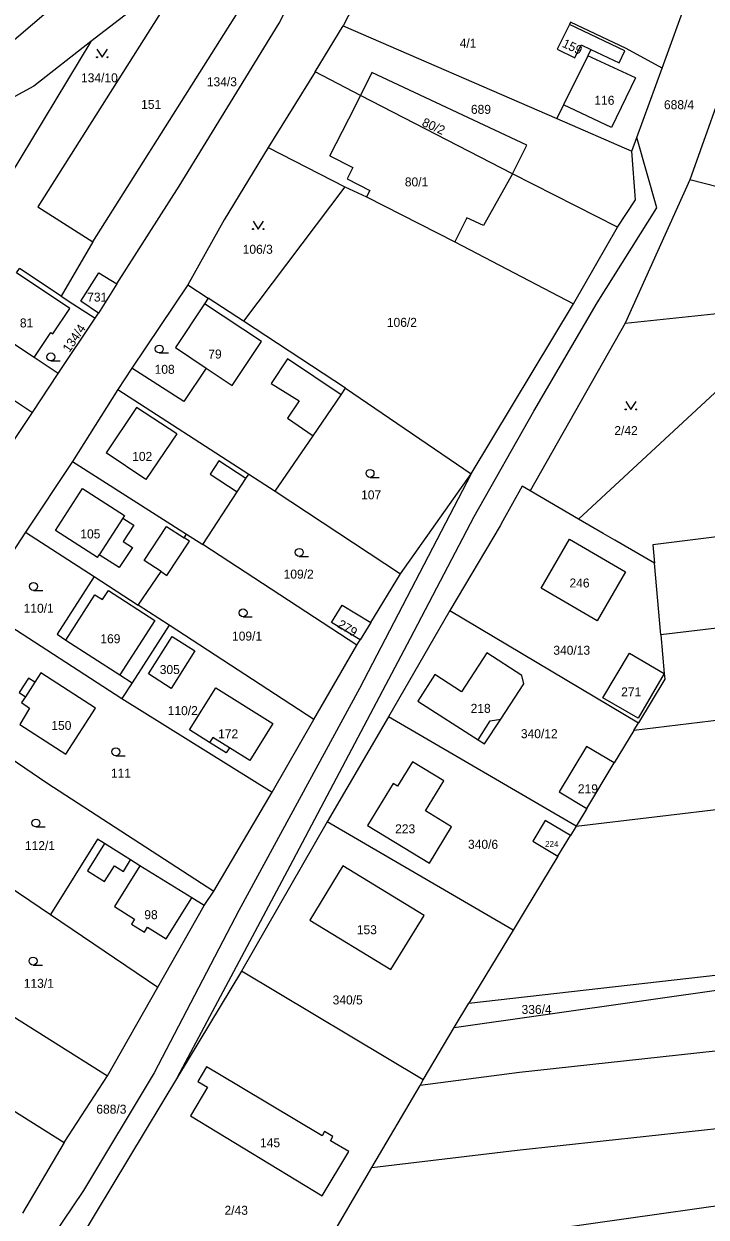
# Model space of a CAD drawing. Extents: x -7483133 to -743907, y -11317770 to -1129777.
# Drawn here: x -746238.8 to -746109.8, y -1131825.9 to -1131600.2 of the extents above; entities that cross this region are included whole.
import ezdxf

# ---------------------------------------------------------------- set-up
doc = ezdxf.new("R2010")
doc.units = 0
for name, color, linetype in [('Hranice parcel', 7, 'Continuous'), ('Parcelní čísla', 7, 'Continuous'), ('Vnitřní kresba', 7, 'Continuous'), ('Značky kultur', 7, 'Continuous')]:
    doc.layers.add(name, color=color, linetype=linetype)

msp = doc.modelspace()

# ---------------------------------------------------------------- linework, layer by layer
at = {"layer": 'Hranice parcel'}
for p, q in [((-746169.3, -1131582.67), (-746178.46, -1131600.58)), ((-746209.75, -1131590.87), (-746226.17, -1131603.55)), ((-746118.15, -1131608.57), (-746111.97, -1131591.58)), ((-746183.74, -1131609.25), (-746178.46, -1131600.58)), ((-746178.46, -1131600.58), (-746138.05, -1131618.07)), ((-746135.43, -1131599.84), (-746135.65, -1131600.29)), ((-746226.17, -1131603.55), (-746248.59, -1131640.59)), ((-746104.52, -1131606.12), (-746112.88, -1131629.7)), ((-746183.74, -1131609.25), (-746192.62, -1131623.6)), ((-746175.19, -1131613.74), (-746183.74, -1131609.25)), ((-746122.9, -1131621.67), (-746118.15, -1131608.57)), ((-746146.41, -1131628.53), (-746175.19, -1131613.74)), ((-746138.05, -1131618.07), (-746123.85, -1131624.29)), ((-746123.85, -1131624.29), (-746122.9, -1131621.67)), ((-746192.62, -1131623.6), (-746178.11, -1131631.02)), ((-746126.56, -1131638.66), (-746146.41, -1131628.53)), ((-746112.88, -1131629.7), (-746125.11, -1131656.77)), ((-746096.04, -1131633.97), (-746112.88, -1131629.7)), ((-746178.11, -1131631.02), (-746197.29, -1131656.44)), ((-746134.91, -1131653.16), (-746126.56, -1131638.66)), ((-746225.82, -1131641.41), (-746231.78, -1131651.66)), ((-746231.78, -1131651.66), (-746239.66, -1131646.47)), ((-746221.25, -1131649.38), (-746224.73, -1131654.87)), ((-746207.82, -1131649.53), (-746218.4, -1131665.32)), ((-746207.82, -1131649.53), (-746203.97, -1131652.06)), ((-746203.97, -1131652.06), (-746204.68, -1131653.13)), ((-746197.29, -1131656.44), (-746203.97, -1131652.06)), ((-746154.22, -1131685.29), (-746134.91, -1131653.16)), ((-746125.11, -1131656.77), (-746090.01, -1131653.11)), ((-746225.37, -1131655.87), (-746224.73, -1131654.87)), ((-746232.33, -1131666.33), (-746225.37, -1131655.87)), ((-746178.01, -1131669.1), (-746197.29, -1131656.44)), ((-746125.11, -1131656.77), (-746143.09, -1131688.51)), ((-746254.86, -1131661.98), (-746237.23, -1131673.69)), ((-746237.23, -1131673.69), (-746232.33, -1131666.33)), ((-746218.4, -1131665.32), (-746221.07, -1131669.31)), ((-746208.6, -1131671.63), (-746218.4, -1131665.32)), ((-746133.92, -1131693.84), (-746104.37, -1131666.43)), ((-746221.07, -1131669.31), (-746229.64, -1131682.94)), ((-746221.07, -1131669.31), (-746196.29, -1131685.32)), ((-746178.84, -1131670.33), (-746178.01, -1131669.1)), ((-746178.01, -1131669.1), (-746154.22, -1131685.29)), ((-746184.1, -1131678.09), (-746178.84, -1131670.33)), ((-746248.85, -1131691.18), (-746237.23, -1131673.69)), ((-746191.3, -1131688.55), (-746184.1, -1131678.09)), ((-746229.64, -1131682.94), (-746238.54, -1131696.32)), ((-746229.64, -1131682.94), (-746208.05, -1131696.69)), ((-746198.48, -1131688.67), (-746196.84, -1131686.16)), ((-746196.84, -1131686.16), (-746196.29, -1131685.32)), ((-746196.29, -1131685.32), (-746191.3, -1131688.55)), ((-746167.6, -1131704.18), (-746154.22, -1131685.29)), ((-746012.9, -1131685.16), (-746119.9, -1131698.71)), ((-746205.01, -1131698.62), (-746198.48, -1131688.67)), ((-746191.3, -1131688.55), (-746167.6, -1131704.18)), ((-746133.92, -1131693.84), (-746143.09, -1131688.51)), ((-746238.54, -1131696.32), (-746247.57, -1131710.13)), ((-746238.54, -1131696.32), (-746225.54, -1131704.73)), ((-746211.79, -1131704.5), (-746207.53, -1131698.01)), ((-746208.05, -1131696.69), (-746205.01, -1131698.62)), ((-746175.84, -1131717.7), (-746205.01, -1131698.62)), ((-746119.9, -1131698.71), (-746119.59, -1131702.16)), ((-746118.38, -1131715.73), (-746119.59, -1131702.16)), ((-746225.54, -1131704.73), (-746232.57, -1131715.63)), ((-746225.54, -1131704.73), (-746217.23, -1131710.1)), ((-746173.21, -1131713.39), (-746167.6, -1131704.18)), ((-746247.57, -1131710.13), (-746220.28, -1131727.78)), ((-746211.35, -1131713.91), (-746217.23, -1131710.1)), ((-746180.67, -1131713.43), (-746178.65, -1131710.15)), ((-746178.65, -1131710.15), (-746173.21, -1131713.39)), ((-746158.27, -1131711.14), (-746169.89, -1131731.23)), ((-746158.27, -1131711.14), (-746122.58, -1131732.37)), ((-746211.35, -1131713.91), (-746218.35, -1131724.78)), ((-746183.97, -1131731.72), (-746211.35, -1131713.91)), ((-746175.23, -1131716.7), (-746180.67, -1131713.43)), ((-746173.21, -1131713.39), (-746175.23, -1131716.7)), ((-746175.84, -1131717.7), (-746175.23, -1131716.7)), ((-746118.38, -1131715.73), (-746117.73, -1131723.06)), ((-746183.97, -1131731.72), (-746175.84, -1131717.7)), ((-746009.74, -1131720.07), (-746123.47, -1131733.84)), ((-746220.68, -1131723.28), (-746218.35, -1131724.78)), ((-746218.35, -1131724.78), (-746220.28, -1131727.78)), ((-746220.28, -1131727.78), (-746191.89, -1131745.5)), ((-746191.89, -1131745.5), (-746183.97, -1131731.72)), ((-746169.89, -1131731.23), (-746181.5, -1131751.09)), ((-746134.41, -1131751.93), (-746169.89, -1131731.23)), ((-746123.47, -1131733.84), (-746122.58, -1131732.37)), ((-746123.47, -1131733.84), (-746127.17, -1131739.96)), ((-746132.45, -1131736.84), (-746137.57, -1131745.44)), ((-746134.41, -1131751.93), (-746008.22, -1131736.82)), ((-746127.17, -1131739.96), (-746132.45, -1131736.84)), ((-746132.37, -1131748.55), (-746127.17, -1131739.96)), ((-746202.88, -1131764.19), (-746191.89, -1131745.5)), ((-746137.57, -1131745.44), (-746132.37, -1131748.55)), ((-746132.37, -1131748.55), (-746134.41, -1131751.93)), ((-746181.5, -1131751.09), (-746197.7, -1131779.34)), ((-746146.31, -1131771.57), (-746181.5, -1131751.09)), ((-746140.23, -1131750.83), (-746142.61, -1131754.73)), ((-746135.47, -1131753.68), (-746140.23, -1131750.83)), ((-746134.41, -1131751.93), (-746135.47, -1131753.68)), ((-746142.61, -1131754.73), (-746137.83, -1131757.57)), ((-746137.83, -1131757.57), (-746135.47, -1131753.68)), ((-746247.71, -1131759.28), (-746233.81, -1131768.65)), ((-746178.52, -1131759.43), (-746184.77, -1131769.7)), ((-746204.77, -1131766.94), (-746207.1, -1131765.49)), ((-746204.77, -1131766.94), (-746202.88, -1131764.19)), ((-746213.53, -1131782.34), (-746204.77, -1131766.94)), ((-746157.45, -1131789.98), (-746005.35, -1131768.4)), ((-746154.67, -1131785.39), (-746005.35, -1131768.4)), ((-746233.81, -1131768.65), (-746213.53, -1131782.34)), ((-746146.31, -1131771.57), (-746154.67, -1131785.39)), ((-746256.85, -1131777.8), (-746223.05, -1131799.15)), ((-746197.7, -1131779.34), (-746209.77, -1131799.39)), ((-746163.29, -1131799.92), (-746197.7, -1131779.34)), ((-746223.05, -1131799.15), (-746213.53, -1131782.34)), ((-746157.45, -1131789.98), (-746154.67, -1131785.39)), ((-746264.99, -1131790.48), (-746231.2, -1131811.77)), ((-746163.29, -1131799.92), (-746157.45, -1131789.98)), ((-746231.2, -1131811.77), (-746223.05, -1131799.15)), ((-746209.77, -1131799.39), (-746228.3, -1131830.15)), ((-746163.91, -1131800.98), (-746163.29, -1131799.92)), ((-746173.02, -1131816.46), (-746163.91, -1131800.98)), ((-746231.2, -1131811.77), (-746239.12, -1131825.11)), ((-746182.24, -1131832.12), (-746173.02, -1131816.46))]:
    msp.add_line(p, q, dxfattribs=at)
for points in [[(-746221.25, -1131649.38), (-746209.49, -1131630.87), (-746190.58, -1131600.07), (-746179.04, -1131577.6), (-746173.33, -1131568.01)], [(-746196.48, -1131579.32), (-746203.74, -1131591.04), (-746207.17, -1131588.88), (-746236.19, -1131634.81), (-746225.82, -1131641.41)], [(-746225.82, -1131641.41), (-746196.77, -1131595.45), (-746188.95, -1131583.07)], [(-746220.35, -1131585.87), (-746245.48, -1131607.32), (-746260.07, -1131614.14)], [(-746135.65, -1131600.29), (-746137.95, -1131605), (-746134.65, -1131606.61), (-746133.46, -1131604.17), (-746131.63, -1131605.04)], [(-746131.63, -1131605.04), (-746126.28, -1131607.58), (-746125.18, -1131605.31), (-746135.65, -1131600.29)], [(-746118.15, -1131608.57), (-746124.96, -1131604.86), (-746135.43, -1131599.84)], [(-746226.17, -1131603.55), (-746236.96, -1131611.95), (-746251.98, -1131620.08)], [(-746131.63, -1131605.04), (-746132.2, -1131606.23), (-746136.79, -1131615.51), (-746138.05, -1131618.07)], [(-746146.41, -1131628.53), (-746143.73, -1131623.16), (-746173.04, -1131609.37), (-746175.19, -1131613.74)], [(-746209.77, -1131799.39), (-746188.47, -1131759.43), (-746165.71, -1131716.39), (-746153.65, -1131693.34), (-746142.41, -1131673.43), (-746130.42, -1131652.96), (-746119.1, -1131634.98), (-746122.9, -1131621.67)], [(-746192.62, -1131623.6), (-746200.96, -1131637.27), (-746207.82, -1131649.53)], [(-746126.56, -1131638.66), (-746123.16, -1131633.44), (-746123.85, -1131624.29)], [(-746178.11, -1131631.02), (-746174.04, -1131632.93), (-746157.34, -1131641.42), (-746134.91, -1131653.16)], [(-746232.33, -1131666.33), (-746236.91, -1131663.29), (-746233.75, -1131658.54), (-746233.36, -1131658.8), (-746230.15, -1131654.01), (-746240.2, -1131647.27), (-746239.66, -1131646.47)], [(-746224.73, -1131654.87), (-746228.08, -1131652.63), (-746224.65, -1131647.29), (-746221.25, -1131649.38)], [(-746231.78, -1131651.66), (-746229.55, -1131653.12), (-746225.37, -1131655.87)], [(-746204.68, -1131653.13), (-746210.15, -1131661.38), (-746204.34, -1131665.28), (-746208.6, -1131671.63)], [(-746154.22, -1131685.29), (-746175.35, -1131725.88), (-746198.19, -1131767.85), (-746214.17, -1131798.54), (-746227.58, -1131820.8), (-746249.27, -1131852.92), (-746268.11, -1131879.9), (-746296.61, -1131921.49), (-746301.25, -1131926.61)], [(-746143.09, -1131688.51), (-746144.59, -1131687.64), (-746148.26, -1131694.19), (-746148.79, -1131695.13), (-746158.27, -1131711.14)], [(-746119.59, -1131702.16), (-746127.06, -1131697.82), (-746129.27, -1131696.54), (-746133.92, -1131693.84)], [(-746207.53, -1131698.01), (-746208.52, -1131697.37), (-746208.05, -1131696.69)], [(-746125.05, -1131703.81), (-746130.42, -1131713.06), (-746140.98, -1131706.93), (-746135.62, -1131697.67), (-746125.05, -1131703.81)], [(-746011.28, -1131703.02), (-746082.88, -1131711.52), (-746090.83, -1131712.46), (-746118.38, -1131715.73)], [(-746217.23, -1131710.1), (-746212.9, -1131703.77), (-746211.79, -1131704.5)], [(-746232.57, -1131715.63), (-746230.88, -1131716.72), (-746220.68, -1131723.28)], [(-746206.49, -1131718.76), (-746210.97, -1131725.86), (-746215.29, -1131723.08), (-746210.77, -1131716.05), (-746206.49, -1131718.76)], [(-746161.12, -1131723.26), (-746164.36, -1131728.28), (-746152.94, -1131735.58), (-746151.74, -1131736.35), (-746148.66, -1131731.66), (-746144.31, -1131725.02), (-746144.66, -1131723.4), (-746151.26, -1131719.11), (-746156.08, -1131726.53), (-746161.12, -1131723.26)], [(-746117.73, -1131723.06), (-746122.65, -1131731.51), (-746129.35, -1131727.65), (-746124.3, -1131719.23), (-746117.73, -1131723.06)], [(-746230.93, -1131738.3), (-746225.29, -1131729.6), (-746235.61, -1131722.9), (-746236.77, -1131724.69), (-746237.95, -1131723.93), (-746239.73, -1131726.67), (-746238.56, -1131727.43), (-746239.28, -1131728.55), (-746237.75, -1131729.59), (-746239.58, -1131732.69), (-746230.93, -1131738.3)], [(-746117.73, -1131723.06), (-746117.64, -1131724.09), (-746122.58, -1131732.37)], [(-746199.96, -1131737.11), (-746200.56, -1131738.06), (-746203.72, -1131736.08), (-746207.52, -1131733.7), (-746202.54, -1131725.73), (-746191.73, -1131732.48), (-746196.12, -1131739.51), (-746199.96, -1131737.11)], [(-746241.4, -1131739.01), (-746234.47, -1131743.75), (-746202.88, -1131764.19)], [(-746162.14, -1131758.91), (-746157.95, -1131752.03), (-746162.91, -1131749), (-746159.44, -1131743.32), (-746165.34, -1131739.72), (-746168.15, -1131744.36), (-746169.01, -1131743.85), (-746173.86, -1131751.77), (-746162.14, -1131758.91)], [(-746223.6, -1131755.22), (-746224.93, -1131754.39), (-746233.81, -1131768.65)], [(-746207.1, -1131765.49), (-746216.88, -1131759.41), (-746218.64, -1131758.31), (-746223.6, -1131755.22)], [(-746184.77, -1131769.7), (-746169.46, -1131779.05), (-746163.11, -1131768.8), (-746178.52, -1131759.43)], [(-746137.83, -1131757.57), (-746144.01, -1131767.78), (-746146.31, -1131771.57)], [(-745872.82, -1131767.1), (-745913.22, -1131772.23), (-746038.67, -1131786.65), (-746091.32, -1131792.64), (-746145.12, -1131798.49), (-746163.91, -1131800.98)], [(-746173.02, -1131816.46), (-746145.54, -1131813.2), (-746104.87, -1131808.78), (-746061.62, -1131803.78), (-746009.82, -1131797.07), (-745872.32, -1131782.29)], [(-746180.84, -1131811.4), (-746180.38, -1131810.62), (-746181.95, -1131809.69), (-746182.41, -1131810.46), (-746202.46, -1131798.53), (-746204.31, -1131797.43), (-746205.95, -1131800.2), (-746204.11, -1131801.3), (-746207.33, -1131806.71)], [(-746182.24, -1131832.12), (-746144.56, -1131828.9), (-746105.32, -1131823.34), (-745952.05, -1131805.35), (-745871.83, -1131797.13)], [(-746207.33, -1131806.71), (-746182.44, -1131821.82), (-746177.39, -1131813.45), (-746180.84, -1131811.4)]]:
    msp.add_lwpolyline(points, dxfattribs=at)
at = {"layer": 'Vnitřní kresba'}
for p, q in [((-746123.14, -1131610.41), (-746132.2, -1131606.23)), ((-746123.14, -1131610.41), (-746127.73, -1131619.82)), ((-746176.18, -1131615.83), (-746175.19, -1131613.74)), ((-746180.96, -1131625.14), (-746176.18, -1131615.83)), ((-746127.73, -1131619.82), (-746136.79, -1131615.51)), ((-746180.96, -1131625.14), (-746176.62, -1131627.37)), ((-746176.62, -1131627.37), (-746177.72, -1131629.52)), ((-746146.41, -1131628.53), (-746151.91, -1131638.33)), ((-746177.72, -1131629.52), (-746173.42, -1131631.72)), ((-746173.42, -1131631.72), (-746174.04, -1131632.93)), ((-746155.06, -1131636.85), (-746157.34, -1131641.42)), ((-746151.91, -1131638.33), (-746155.06, -1131636.85)), ((-746193.87, -1131660.27), (-746204.68, -1131653.13)), ((-746236.91, -1131663.29), (-746244.15, -1131658.48)), ((-746199.42, -1131668.58), (-746193.87, -1131660.27)), ((-746188.96, -1131663.55), (-746192.08, -1131668.2)), ((-746178.84, -1131670.33), (-746188.96, -1131663.55)), ((-746204.34, -1131665.28), (-746199.42, -1131668.58)), ((-746192.08, -1131668.2), (-746186.79, -1131671.5)), ((-746186.79, -1131671.5), (-746189, -1131674.77)), ((-746217.55, -1131672.77), (-746223.27, -1131681.3)), ((-746209.89, -1131677.72), (-746217.55, -1131672.77)), ((-746189, -1131674.77), (-746184.1, -1131678.09)), ((-746209.89, -1131677.72), (-746215.75, -1131686.34)), ((-746215.75, -1131686.34), (-746223.27, -1131681.3)), ((-746201.94, -1131682.81), (-746203.59, -1131685.32)), ((-746196.84, -1131686.16), (-746201.94, -1131682.81)), ((-746203.59, -1131685.32), (-746198.48, -1131688.67)), ((-746232.86, -1131696.03), (-746227.77, -1131688.09)), ((-746227.77, -1131688.09), (-746219.83, -1131693.18)), ((-746220.13, -1131693.65), (-746224.59, -1131700.61)), ((-746219.83, -1131693.18), (-746220.13, -1131693.65)), ((-746220.13, -1131693.65), (-746218.05, -1131694.98)), ((-746224.92, -1131701.12), (-746232.86, -1131696.03)), ((-746218.05, -1131694.98), (-746220.04, -1131698.08)), ((-746216.08, -1131701.68), (-746211.84, -1131695.22)), ((-746211.84, -1131695.22), (-746208.52, -1131697.37)), ((-746220.04, -1131698.08), (-746218.3, -1131699.2)), ((-746224.92, -1131701.12), (-746224.59, -1131700.61)), ((-746220.81, -1131703.03), (-746224.59, -1131700.61)), ((-746218.3, -1131699.2), (-746220.81, -1131703.03)), ((-746212.9, -1131703.77), (-746216.08, -1131701.68)), ((-746223.99, -1131709.08), (-746222.85, -1131707.37)), ((-746222.85, -1131707.37), (-746214.04, -1131713.03)), ((-746230.88, -1131716.72), (-746225.39, -1131708.18)), ((-746225.39, -1131708.18), (-746223.99, -1131709.08)), ((-746214.04, -1131713.03), (-746220.68, -1131723.28)), ((-746236.77, -1131724.69), (-746238.56, -1131727.43)), ((-746152.94, -1131735.58), (-746150.67, -1131732.02)), ((-746150.67, -1131732.02), (-746148.66, -1131731.66)), ((-746203.13, -1131735.12), (-746203.72, -1131736.08)), ((-746199.96, -1131737.11), (-746203.13, -1131735.12)), ((-746223.6, -1131755.22), (-746226.83, -1131760.34)), ((-746223.56, -1131762.38), (-746221.68, -1131759.43)), ((-746216.88, -1131759.41), (-746221.71, -1131767.14)), ((-746221.68, -1131759.43), (-746219.99, -1131760.48)), ((-746219.99, -1131760.48), (-746218.64, -1131758.31)), ((-746226.83, -1131760.34), (-746223.56, -1131762.38)), ((-746211.93, -1131773.21), (-746207.1, -1131765.49)), ((-746221.71, -1131767.14), (-746217.93, -1131769.49)), ((-746217.93, -1131769.49), (-746218.51, -1131770.42)), ((-746218.51, -1131770.42), (-746216.05, -1131771.94)), ((-746216.05, -1131771.94), (-746215.47, -1131771.01)), ((-746215.47, -1131771.01), (-746211.93, -1131773.21))]:
    msp.add_line(p, q, dxfattribs=at)
at = {"layer": 'Značky kultur'}
for p, q in [((-746213.23, -1131662.43), (-746211.48, -1131662.43)), ((-746233.74, -1131663.93), (-746231.99, -1131663.93)), ((-746173.37, -1131685.96), (-746171.62, -1131685.96)), ((-746186.75, -1131700.89), (-746185, -1131700.89)), ((-746237.02, -1131707.33), (-746235.27, -1131707.33)), ((-746197.38, -1131712.32), (-746195.63, -1131712.32)), ((-746221.44, -1131738.59), (-746219.69, -1131738.59)), ((-746236.55, -1131752.07), (-746234.8, -1131752.07)), ((-746237.09, -1131778.18), (-746235.34, -1131778.18))]:
    msp.add_line(p, q, dxfattribs=at)
for points in [[(-746225.01, -1131605), (-746224.01, -1131606.5), (-746223.01, -1131605)], [(-746195.5, -1131637.5), (-746194.5, -1131639), (-746193.5, -1131637.5)], [(-746125.02, -1131671.61), (-746124.02, -1131673.11), (-746123.02, -1131671.61)]]:
    msp.add_lwpolyline(points, dxfattribs=at)
for centre, radius in [((-746225.01, -1131606.5), 0.1), ((-746223.01, -1131606.5), 0.1), ((-746195.5, -1131639), 0.1), ((-746193.5, -1131639), 0.1), ((-746233.74, -1131663.18), 0.75), ((-746213.23, -1131661.68), 0.75), ((-746125.02, -1131673.11), 0.1), ((-746123.02, -1131673.11), 0.1), ((-746173.37, -1131685.21), 0.75), ((-746186.75, -1131700.14), 0.75), ((-746237.02, -1131706.58), 0.75), ((-746197.38, -1131711.57), 0.75), ((-746221.44, -1131737.84), 0.75), ((-746236.55, -1131751.32), 0.75), ((-746237.09, -1131777.43), 0.75)]:
    msp.add_circle(centre, radius, dxfattribs=at)

# ---------------------------------------------------------------- texts
at = {"layer": 'Parcelní čísla'}
for s, height, p in [('4/1', 1.7, (-746156.41, -1131604.7)), ('134/10', 1.7, (-746228.03, -1131611.24)), ('134/3', 1.7, (-746204.23, -1131611.99)), ('151', 1.7, (-746216.66, -1131616.27)), ('116', 1.7, (-746130.94, -1131615.49)), ('688/4', 1.7, (-746117.78, -1131616.33)), ('689', 1.7, (-746154.29, -1131617.21)), ('80/1', 1.7, (-746166.79, -1131630.93)), ('106/3', 1.7, (-746197.45, -1131643.67)), ('731', 1.7, (-746226.86, -1131652.71)), ('106/2', 1.7, (-746170.19, -1131657.49)), ('81', 1.7, (-746239.59, -1131657.6)), ('79', 1.7, (-746203.96, -1131663.48)), ('108', 1.7, (-746214.11, -1131666.37)), ('2/42', 1.7, (-746127.17, -1131677.96)), ('102', 1.7, (-746218.35, -1131682.84)), ('107', 1.7, (-746175.06, -1131690.11)), ('105', 1.7, (-746228.16, -1131697.5)), ('109/2', 1.7, (-746189.71, -1131705.1)), ('246', 1.7, (-746135.65, -1131706.78)), ('110/1', 1.7, (-746238.88, -1131711.56)), ('169', 1.7, (-746224.37, -1131717.32)), ('109/1', 1.7, (-746199.47, -1131716.82)), ('340/13', 1.7, (-746138.7, -1131719.5)), ('305', 1.7, (-746213.14, -1131723.15)), ('271', 1.7, (-746125.87, -1131727.37)), ('110/2', 1.7, (-746211.63, -1131730.92)), ('218', 1.7, (-746154.34, -1131730.49)), ('150', 1.7, (-746233.64, -1131733.72)), ('172', 1.7, (-746202.1, -1131735.3)), ('340/12', 1.7, (-746144.84, -1131735.28)), ('111', 1.7, (-746222.37, -1131742.74)), ('219', 1.7, (-746134.06, -1131745.7)), ('223', 1.7, (-746168.62, -1131753.27)), ('112/1', 1.7, (-746238.64, -1131756.45)), ('340/6', 1.7, (-746154.84, -1131756.2)), ('224', 1.14, (-746140.27, -1131755.85)), ('98', 1.7, (-746216.06, -1131769.51)), ('153', 1.7, (-746175.87, -1131772.35)), ('113/1', 1.7, (-746238.86, -1131782.49)), ('340/5', 1.7, (-746180.44, -1131785.63)), ('336/4', 1.7, (-746144.71, -1131787.43)), ('688/3', 1.7, (-746225.13, -1131806.29)), ('145', 1.7, (-746194.17, -1131812.63)), ('2/43', 1.7, (-746200.89, -1131825.41))]:
    msp.add_text(s, height=height, dxfattribs=at).set_placement(p)
for s, rotation, p in [('159', 335, (-746137.17, -1131604.48)), ('80/2', 336, (-746163.7, -1131619.43)), ('134/4', 56, (-746230.23, -1131662.46)), ('279', 329, (-746179.68, -1131714.2))]:
    msp.add_text(s, height=1.7, rotation=rotation, dxfattribs=at).set_placement(p)

doc.saveas('drawing.dxf')
